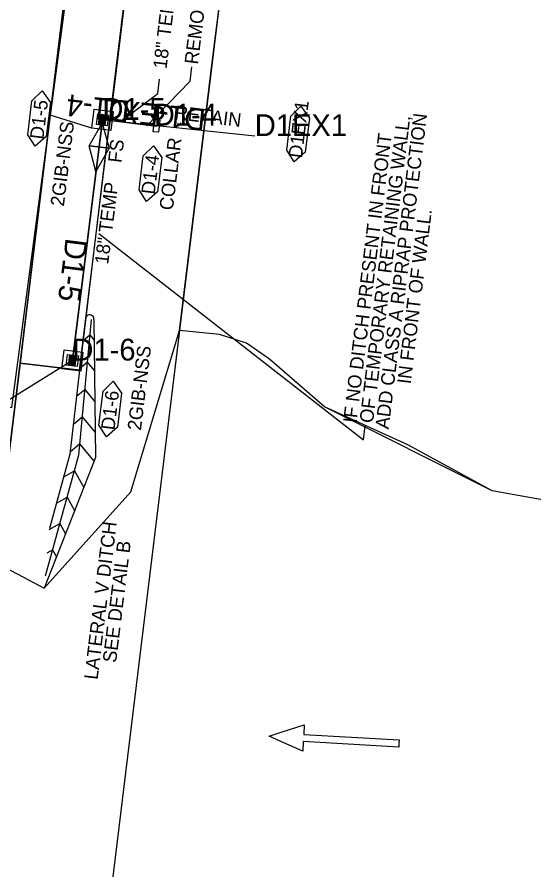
# Model space of a CAD drawing. Extents: x 465700 to 483515, y 488970 to 507540.
# Drawn here: x 481231.5 to 481421.3, y 490088.5 to 490401.6 of the extents above; entities that cross this region are included whole.
import ezdxf

# ---------------------------------------------------------------- set-up
doc = ezdxf.new("R2010")
doc.units = 0
for name, color, linetype in [('Default', 7, 'Continuous'), ('Exist Plan Preparation Drainage Flow Arrows', 7, 'Continuous'), ('Exist Plan Preparation Watershed Blue', 7, 'Continuous'), ('Prop Drainage Structure Box Number Symbol CELL', 7, 'Continuous'), ('Prop Drainage Structure Drop Inlet Grate 2 Narrow Slots and Sag Grates 840 24 CELL', 7, 'Continuous'), ('Prop Drainage Structure Drop Inlet Grate 2 Narrow Slots and Sag Grates 840 24 Label', 7, 'Continuous'), ('Prop Drainage Structure Pipe Collar CELL', 7, 'Continuous'), ('Prop Drainage Structure Pipe Collar Label', 7, 'Continuous'), ('Prop Drainage Structure Pipe CSP 18in', 7, 'Continuous'), ('Prop Drainage Structure Pipe RCP 18in Class III', 7, 'Continuous'), ('Prop Drainage Structure Pipe RCP 18in Class III Label', 7, 'Continuous'), ('Prop Drainage Structure Pipe Stub Out CELL', 7, 'Continuous'), ('Prop Drainage Structure Plot Symbol 20 Scale CELL', 7, 'Continuous'), ('Prop Drainage Structure Plot Symbol 50 Scale CELL', 7, 'Continuous'), ('Prop Drainage Structure Removal Label', 7, 'Continuous'), ('Prop Earthen Structure Base Ditch Lateral Detail Label', 7, 'Continuous'), ('Prop Earthen Structure False Sump CELL', 7, 'Continuous'), ('Prop Earthen Structure False Sump Label', 7, 'Continuous'), ('Prop Earthen Structure Head Ditch', 7, 'Continuous'), ('Prop NEU Channel Block Detail Label', 7, 'Continuous'), ('Scratch_Level_8', 7, 'Continuous')]:
    doc.layers.add(name, color=color, linetype=linetype)

# ---------------------------------------------------------------- blocks, each defined once
blk = doc.blocks.new('Existing ground flow arrow')
at = {"layer": 'Default'}
blk.add_line((2.5, -4.33), (2.5, -4.33), dxfattribs=at)
blk.add_lwpolyline([(-1.29, -47.2), (-1.28, -12.53), (-4.77, -12.53), (-1.65, -4.33), (0, 0), (1.65, -4.33), (4.78, -12.53), (1.28, -12.52), (1.29, -47.19), (0, -47.2)], close=True, dxfattribs=at)

msp = doc.modelspace()

# ---------------------------------------------------------------- linework, layer by layer
at = {"layer": 'Exist Plan Preparation Watershed Blue'}
for points in [[(481178.35, 489921.07), (481181.18, 489944.23), (481192.1, 489942.89), (481199.42, 490002.85), (481223.67, 490201.37), (481232.65, 490274.58), (481301.55, 490839.02), (481357.88, 490832.14), (481339.74, 490683.62), (481315.49, 490485.09), (481303.36, 490385.83), (481279.12, 490187.3), (481254.87, 489988.78), (481242.75, 489889.52)], [(480982.54, 490200.49), (481022.64, 490226.93), (481057.88, 490239.62), (481085.68, 490250.52), (481125.08, 490261.61), (481159, 490262.25), (481229.67, 490258.2), (481254.1, 490443.2), (481288.29, 490738.89), (481339.74, 490683.62), (481381.2, 490650.46), (481429.31, 490629.05), (481609.7, 490592.3), (481802.24, 490660.02), (481819.54, 490679.79), (481842.61, 490718.46), (481669.68, 490775.55), (481613.6, 490791.65)], [(481447.64, 490220.24), (481406.01, 490227.66), (481375.34, 490244.48), (481344.41, 490258.47), (481324.25, 490276.03), (481315.77, 490281.86), (481305.84, 490285.06), (481291.24, 490286.57), (481297.41, 490337.07), (481303.36, 490385.83), (481311.9, 490453.82), (481339.74, 490683.62), (481381.2, 490650.46), (481429.31, 490629.05)], [(481447.64, 490220.24), (481406.01, 490227.66), (481344.41, 490258.47), (481324.25, 490276.03), (481315.77, 490281.86), (481305.84, 490285.06), (481291.24, 490286.57), (481279.12, 490187.3), (481254.87, 489988.78), (481250.18, 489950.39), (481242.75, 489889.52)]]:
    msp.add_lwpolyline(points, dxfattribs=at)
for points in [[(481241.45, 490191.91), (481273.35, 490227.27), (481291.24, 490286.57), (481303.36, 490385.83), (481311.9, 490453.82), (481327.61, 490584.35), (481339.74, 490683.62), (481353.35, 490795.1), (481357.83, 490831.75), (481325.41, 490836.1), (481323.3, 490836.37), (481263.76, 490349.7), (481254.45, 490271.98), (481232.65, 490274.58), (481223.67, 490201.37)], [(481259, 490360.8), (481243.71, 490365.51), (481284.29, 490697.69), (481301.55, 490839.02), (481323.3, 490836.37), (481281, 490489.23), (481265.22, 490360.1)], [(481243.71, 490365.51), (481232.65, 490274.58), (481254.45, 490271.98), (481265.22, 490360.1), (481259, 490360.8)]]:
    msp.add_lwpolyline(points, close=True, dxfattribs=at)
at = {"layer": 'Prop Drainage Structure Box Number Symbol CELL'}
for points in [[(481235.49, 490358.36), (481237.02, 490370.87), (481240.72, 490374.55), (481243.8, 490370.2), (481242.27, 490357.69), (481238.23, 490354.15), (481235.49, 490358.36)], [(481330.57, 490352.68), (481332.1, 490365.2), (481335.8, 490368.88), (481338.88, 490364.53), (481337.35, 490352.01), (481333.31, 490348.48), (481330.57, 490352.68)], [(481276.36, 490338.14), (481277.89, 490350.65), (481281.59, 490354.33), (481284.67, 490349.98), (481283.14, 490337.47), (481279.1, 490333.94), (481276.36, 490338.14)], [(481261.61, 490251.73), (481263.13, 490264.24), (481266.84, 490267.93), (481269.91, 490263.58), (481268.39, 490251.06), (481264.35, 490247.53), (481261.61, 490251.73)]]:
    msp.add_lwpolyline(points, dxfattribs=at)
at = {"layer": 'Prop Drainage Structure Drop Inlet Grate 2 Narrow Slots and Sag Grates 840 24 CELL'}
for p, q in [((481261.74, 490363.99), (481261.74, 490363.99)), ((481262.9, 490363.85), (481262.9, 490363.85)), ((481263.14, 490365.83), (481263.14, 490365.83)), ((481264.06, 490363.71), (481264.06, 490363.71)), ((481262.66, 490361.86), (481262.66, 490361.86)), ((481252.1, 490277.49), (481252.1, 490277.49)), ((481250.7, 490275.64), (481250.7, 490275.64)), ((481251.62, 490273.52), (481251.62, 490273.52)), ((481251.86, 490275.5), (481251.86, 490275.5)), ((481253.02, 490275.36), (481253.02, 490275.36))]:
    msp.add_line(p, q, dxfattribs=at)
for points in [[(481264.3, 490365.69), (481263.82, 490361.72), (481261.5, 490362), (481261.99, 490365.97), (481264.3, 490365.69)], [(481264.23, 490365.64), (481263.76, 490361.79), (481261.57, 490362.06), (481262.04, 490365.91), (481264.23, 490365.64)], [(481263.99, 490363.71), (481263.75, 490361.8), (481261.58, 490362.07), (481261.81, 490363.97), (481263.99, 490363.71)], [(481264.22, 490365.63), (481263.99, 490363.73), (481261.82, 490363.99), (481262.05, 490365.89), (481264.22, 490365.63)], [(481263.76, 490363.34), (481263.74, 490363.17), (481261.93, 490363.39), (481261.95, 490363.57), (481263.76, 490363.34)], [(481263.79, 490363.64), (481263.77, 490363.46), (481261.96, 490363.68), (481261.98, 490363.86), (481263.79, 490363.64)], [(481263.84, 490364.01), (481263.82, 490363.84), (481262.01, 490364.06), (481262.03, 490364.23), (481263.84, 490364.01)], [(481263.88, 490364.31), (481263.85, 490364.13), (481262.04, 490364.35), (481262.07, 490364.53), (481263.88, 490364.31)], [(481263.91, 490364.6), (481263.89, 490364.43), (481262.08, 490364.65), (481262.1, 490364.82), (481263.91, 490364.6)], [(481263.95, 490364.9), (481263.93, 490364.72), (481262.12, 490364.94), (481262.14, 490365.12), (481263.95, 490364.9)], [(481263.98, 490365.19), (481263.96, 490365.01), (481262.15, 490365.24), (481262.17, 490365.41), (481263.98, 490365.19)], [(481264.02, 490365.49), (481264, 490365.31), (481262.19, 490365.53), (481262.21, 490365.71), (481264.02, 490365.49)], [(481263.61, 490362.17), (481263.59, 490361.99), (481261.78, 490362.21), (481261.8, 490362.39), (481263.61, 490362.17)], [(481263.65, 490362.46), (481263.63, 490362.29), (481261.82, 490362.51), (481261.84, 490362.68), (481263.65, 490362.46)], [(481263.69, 490362.76), (481263.66, 490362.58), (481261.86, 490362.8), (481261.88, 490362.98), (481263.69, 490362.76)], [(481263.72, 490363.05), (481263.7, 490362.87), (481261.89, 490363.1), (481261.91, 490363.27), (481263.72, 490363.05)], [(481253.26, 490277.35), (481252.78, 490273.38), (481250.46, 490273.66), (481250.95, 490277.63), (481253.26, 490277.35)], [(481253.19, 490277.29), (481252.72, 490273.45), (481250.53, 490273.71), (481251, 490277.56), (481253.19, 490277.29)], [(481253.18, 490277.28), (481252.95, 490275.38), (481250.78, 490275.65), (481251.01, 490277.55), (481253.18, 490277.28)], [(481252.8, 490275.67), (481252.78, 490275.49), (481250.97, 490275.71), (481250.99, 490275.89), (481252.8, 490275.67)], [(481252.84, 490275.96), (481252.81, 490275.78), (481251.01, 490276.01), (481251.03, 490276.18), (481252.84, 490275.96)], [(481252.87, 490276.26), (481252.85, 490276.08), (481251.04, 490276.3), (481251.06, 490276.48), (481252.87, 490276.26)], [(481252.91, 490276.55), (481252.89, 490276.37), (481251.08, 490276.6), (481251.1, 490276.77), (481252.91, 490276.55)], [(481252.94, 490276.84), (481252.92, 490276.67), (481251.11, 490276.89), (481251.13, 490277.07), (481252.94, 490276.84)], [(481252.98, 490277.14), (481252.96, 490276.96), (481251.15, 490277.18), (481251.17, 490277.36), (481252.98, 490277.14)], [(481252.95, 490275.36), (481252.71, 490273.46), (481250.54, 490273.72), (481250.78, 490275.62), (481252.95, 490275.36)], [(481252.57, 490273.82), (481252.55, 490273.64), (481250.74, 490273.87), (481250.77, 490274.04), (481252.57, 490273.82)], [(481252.61, 490274.12), (481252.59, 490273.94), (481250.78, 490274.16), (481250.8, 490274.34), (481252.61, 490274.12)], [(481252.65, 490274.41), (481252.63, 490274.23), (481250.82, 490274.46), (481250.84, 490274.63), (481252.65, 490274.41)], [(481252.68, 490274.7), (481252.66, 490274.53), (481250.85, 490274.75), (481250.87, 490274.93), (481252.68, 490274.7)], [(481252.72, 490275), (481252.7, 490274.82), (481250.89, 490275.04), (481250.91, 490275.22), (481252.72, 490275)], [(481252.75, 490275.29), (481252.73, 490275.12), (481250.92, 490275.34), (481250.95, 490275.51), (481252.75, 490275.29)]]:
    msp.add_lwpolyline(points, dxfattribs=at)
at = {"layer": 'Prop Drainage Structure Pipe Collar CELL'}
msp.add_line((481281.75, 490361.76), (481281.75, 490361.76), dxfattribs=at)
msp.add_line((481281.75, 490361.76), (481281.75, 490361.76), dxfattribs=at)
msp.add_lwpolyline([(481280.98, 490361.85), (481281.75, 490361.76), (481282.02, 490364.01), (481283.99, 490363.77), (481283.44, 490359.27), (481281.47, 490359.51), (481281.47, 490359.51), (481281.75, 490361.76)], dxfattribs=at)
msp.add_lwpolyline([(481282.02, 490364.01), (481283.99, 490363.77), (481283.44, 490359.27), (481281.47, 490359.51)], close=True, dxfattribs=at)
at = {"layer": 'Prop Drainage Structure Pipe CSP 18in'}
msp.add_line((481251.86, 490275.5), (481148.7, 490211.95), dxfattribs=at)
at = {"layer": 'Prop Drainage Structure Pipe RCP 18in Class III'}
for p in [(481251.86, 490275.5), (481282.71, 490361.43)]:
    msp.add_line(p, (481262.9, 490363.85), dxfattribs=at)
at = {"layer": 'Prop Drainage Structure Pipe Stub Out CELL'}
msp.add_line((481318.82, 490357.89), (481318.82, 490357.89), dxfattribs=at)
msp.add_line((481318.82, 490357.89), (481318.82, 490357.89), dxfattribs=at)
msp.add_lwpolyline([(481318.8, 490357.89), (481318.82, 490357.9), (481318.83, 490357.89), (481318.81, 490357.87), (481318.8, 490357.89)], dxfattribs=at)
at = {"layer": 'Prop Drainage Structure Plot Symbol 20 Scale CELL'}
for points in [[(481265.13, 490365.59), (481264.64, 490361.62), (481260.67, 490362.11), (481261.16, 490366.08)], [(481254.09, 490277.25), (481253.6, 490273.27), (481249.63, 490273.76), (481250.12, 490277.73)]]:
    msp.add_lwpolyline(points, close=True, dxfattribs=at)
at = {"layer": 'Prop Drainage Structure Plot Symbol 50 Scale CELL'}
for points in [[(481266.8, 490366.9), (481265.95, 490359.95), (481259, 490360.8), (481259.85, 490367.75)], [(481255.76, 490278.55), (481254.91, 490271.6), (481247.96, 490272.45), (481248.81, 490279.4)]]:
    msp.add_lwpolyline(points, close=True, dxfattribs=at)
at = {"layer": 'Prop Drainage Structure Removal Label'}
msp.add_lwpolyline([(481279.22, 490361.71), (481295.09, 490378.01), (481295.73, 490383.26)], dxfattribs=at)
at = {"layer": 'Prop Earthen Structure False Sump CELL'}
msp.add_lwpolyline([(481260.43, 490344.92), (481258.02, 490354.33), (481262.76, 490362.69), (481265.35, 490353.43), (481258.02, 490354.33), (481265.35, 490353.43), (481260.43, 490344.92)], dxfattribs=at)
at = {"layer": 'Prop Earthen Structure Head Ditch'}
for points in [[(481259.73, 490290.42), (481260.41, 490239.96), (481241.45, 490191.95)], [(481258.75, 490290.54), (481254.15, 490240.72), (481241.85, 490196.31)], [(481258.75, 490290.54), (481254.15, 490240.72), (481241.85, 490196.31)], [(481256.74, 490290.69), (481254.45, 490271.98), (481250.98, 490241.11), (481243.46, 490213.84)], [(481255.78, 490282.87), (481258.23, 490284.9), (481259.83, 490282.97)], [(481254.53, 490272.59), (481257.3, 490274.89), (481259.98, 490271.67)], [(481253.37, 490262.39), (481256.38, 490264.89), (481260.14, 490260.37)], [(481252.23, 490252.19), (481255.46, 490254.88), (481260.29, 490249.06)], [(481251.08, 490242), (481254.53, 490244.87), (481259.83, 490238.49)], [(481248.7, 490232.85), (481252.58, 490235.05), (481256.08, 490228.87)], [(481246.03, 490223.18), (481249.9, 490225.37), (481252.7, 490220.42)], [(481243.36, 490213.5), (481247.21, 490215.68), (481249.34, 490211.93)], [(481242.64, 490204.92), (481244.53, 490206), (481245.98, 490203.43)]]:
    msp.add_lwpolyline(points, dxfattribs=at)
msp.add_arc((481258.25, 490290.76), 1.52, 346.72, 182.841, dxfattribs=at)
at = {"layer": 'Prop NEU Channel Block Detail Label'}
for points in [[(481269.78, 490363.33), (481283.19, 490373.55), (481283.83, 490378.8)], [(481261.55, 490322.15), (481358.72, 490246.38), (481359.36, 490251.58)]]:
    msp.add_lwpolyline(points, dxfattribs=at)
at = {"layer": 'Scratch_Level_8'}
for p, q in [((481262.9, 490363.85), (481251.86, 490275.5)), ((481281.75, 490361.76), (481262.9, 490363.85)), ((481318.82, 490357.89), (481281.75, 490361.76)), ((481251.86, 490275.5), (481148.7, 490211.95))]:
    msp.add_line(p, q, dxfattribs=at)

# ---------------------------------------------------------------- block references
at = {"layer": 'Exist Plan Preparation Drainage Flow Arrows', "xscale": 1.0124070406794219, "yscale": 1.0124070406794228, "rotation": 86.76596956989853}
msp.add_blockref('Existing ground flow arrow', (481324.07, 490137.62), dxfattribs=at)

# ---------------------------------------------------------------- texts
at = {"layer": 'Prop Drainage Structure Box Number Symbol CELL'}
for s, p in [('D1-5', (481241.2, 490356.49)), ('D1EX1', (481336.13, 490349.64)), ('D1-4', (481282.07, 490336.31)), ('D1-6', (481267.3, 490249.78))]:
    msp.add_text(s, height=5, rotation=83.0394, dxfattribs=at).set_placement(p)
at = {"layer": 'Prop Drainage Structure Drop Inlet Grate 2 Narrow Slots and Sag Grates 840 24 Label'}
for p in [(481248.74, 490331.93), (481277.02, 490249.65)]:
    msp.add_text('2GIB-NSS', height=5, rotation=83.0423, dxfattribs=at).set_placement(p)
at = {"layer": 'Prop Drainage Structure Pipe Collar Label'}
for s, rotation, p in [('RETAIN', 353.0365, (481289.24, 490364.18)), ('COLLAR', 83.0365, (481288.73, 490330.46))]:
    msp.add_text(s, height=5, rotation=rotation, dxfattribs=at).set_placement(p)
at = {"layer": 'Prop Drainage Structure Pipe RCP 18in Class III Label'}
for rotation, p in [(83.0366, (481286.42, 490382.39)), (82.8774, (481264.99, 490310.63))]:
    msp.add_text('18" TEMP', height=5, rotation=rotation, dxfattribs=at).set_placement(p)
at = {"layer": 'Prop Drainage Structure Pipe Stub Out CELL'}
msp.add_text('SO', height=0.0104, rotation=353.0365, dxfattribs=at).set_placement((481318.81, 490357.88))
at = {"layer": 'Prop Drainage Structure Removal Label'}
msp.add_text('REMOVE 9\' EX. 18" CMP', height=5, rotation=83.0366, dxfattribs=at).set_placement((481297.97, 490384.04))
at = {"layer": 'Prop Earthen Structure Base Ditch Lateral Detail Label'}
for s, p in [('OF TEMPORARY RETAINING WALL, ', (481362.23, 490252.38)), ('ADD CLASS A RIPRAP PROTECTION', (481368, 490250.13)), ('IF NO DITCH PRESENT IN FRONT', (481356.19, 490252.38)), ('IN FRONT OF WALL.', (481376.07, 490266.69)), ('LATERAL V DITCH', (481261.11, 490158.17)), ('SEE DETAIL B', (481267.92, 490164.39))]:
    msp.add_text(s, height=5, rotation=83.0394, dxfattribs=at).set_placement(p)
at = {"layer": 'Prop Earthen Structure False Sump Label'}
msp.add_text('FS', height=5, rotation=83.0423, dxfattribs=at).set_placement((481269.87, 490347.9))
at = {"layer": 'Scratch_Level_8'}
for s, rotation, p in [('D1-4', 173.677, (481273.21, 490370.76)), ('D1-EX1', 174.0379, (481301.11, 490367.78)), ('D1-5', 262.8774, (481249.44, 490320.67))]:
    msp.add_text(s, height=8, rotation=rotation, dxfattribs=at).set_placement(p)
for s, p in [('D1-5', (481262.9, 490363.85)), ('D1-4', (481281.75, 490361.76)), ('D1EX1', (481318.82, 490357.89)), ('D1-6', (481251.86, 490275.5))]:
    msp.add_text(s, height=8, dxfattribs=at).set_placement(p)

doc.saveas('drawing.dxf')
